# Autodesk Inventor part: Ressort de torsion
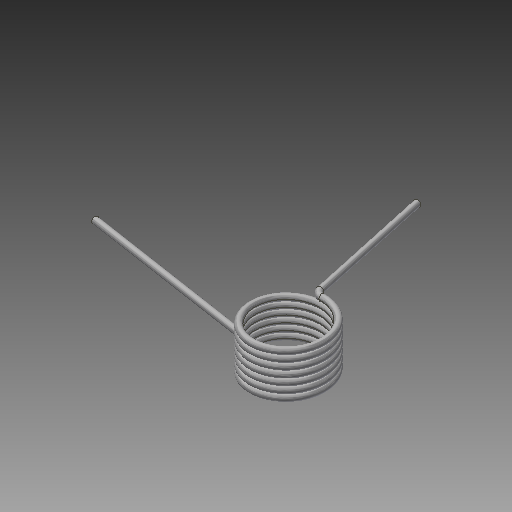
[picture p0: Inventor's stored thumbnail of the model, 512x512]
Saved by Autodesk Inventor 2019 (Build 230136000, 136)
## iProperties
Created: 2018-06
Part Number: Ressort de torsion
Material: Steel
Document SubType Name: Modeling
Designer: Fabian Perrée
Density: 1 g/cm^3
Appearance: Steel
CustomPartVersion: 1
Author: Fabian Perrée
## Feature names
1. Main Coil(R)
2. Bras de fonctionnement droit (droite)
3. Bras de fonctionnement droit axial (droite)
4. Bras de fonctionnement d'accrochage (droite)
5. Bras de fonctionnement d'accrochage interne (droite)
6. Bras de support droit (droit)
7. Bras de support droit axial (droite)
8. Bras de support d'accrochage (droite)
9. Bras de support d'accrochage interne (droite)
10. Main Coil(L)
11. StraightWorkingArm(L)
12. Bras de fonctionnement droit axial (gauche)
13. Bras de fonctionnement d'accrochage (gauche)
14. Bras de fonctionnement d'accrochage interne (gauche)
15. Bras de support droit (gauche)
16. Bras de support droit axial (gauche)
17. Bras de support d'accrochage (gauche)
18. Bras de support d'accrochage interne (gauche)
## Parameters: da_d = 0.5 mm, da_D2 = 5 mm, da_ni = 67.58776 mm, da_t = 0.525 mm, Not_rightdir = 0, da_r1 = 0.5 mm, Lr2 = 15 mm, da_r2 = 0.5 mm, const_zero = 0, d0 = 0.125 mm, d1 = 2.75 mm, d2 = 0.525 mm, d4 = 67.58776 mm, d5 = 0, d6 = 90 deg, d7 = 90 deg, d8 = 0, d9 = 0, d10 = 0.5 mm, d11 = 0, d13 = 0.5 mm, d14 = 0, d15 = 0.5 mm, d17 = 0, d19 = 0, d20 = 0.5 mm, d22 = 0, d28 = 0.525 mm, d30 = 67.58776 mm, d31 = 0, d32 = 90 deg, d33 = 90 deg, d34 = 0, d35 = 0, d36 = 0.5 mm, d37 = 0, d39 = 0.5 mm, d40 = 0, d41 = 0.5 mm, d43 = 0, d45 = 0, d46 = 0.5 mm, d48 = 0, leftWorkType = 0, leftSupportType = 0, d54 = 90 deg, d56 = 0.5 mm, d57 = 10.25 mm, d58 = 0, d59 = 0 mm, d60 = 0, da_Lr2 = 15 mm, d63 = 90 deg, d64 = 0.5 mm, d65 = 15.25 mm, d66 = 0, Is_w_HardEnd = 0, Is_s_HardEnd = 0, d67 = 0 mm, d69 = 0, d78 = 90 deg, d79 = 0.5 mm, d80 = 10.25 mm, d81 = 0, d82 = 0 mm, d84 = 0, d85 = 90 deg, d86 = 0.5 mm, d87 = 15.25 mm, d88 = 0, d89 = 0 mm, d91 = 0, d101 = 15 mm, d102 = 6 mm, d104 = 6 mm, d105 = 15 mm, d106 = 5 mm, d108 = 5 mm, d109 = 15 mm, d110 = 5 mm, d112 = 5 mm, d113 = 15 mm, d114 = 6 mm, d116 = 6 mm, d117 = 15 mm, d119 = 15 mm, Is_s_Internal = 0, Is_w_Internal = 0, d120 = 0, d121 = 0, d122 = 0, d123 = 0, d124 = 0, d125 = 0, d126 = 0, d127 = 0, d128 = 0, d129 = 0, d130 = 0, d131 = 0, d132 = 0, d133 = 0, d134 = 0, d135 = 0, d136 = 0, d137 = 0
